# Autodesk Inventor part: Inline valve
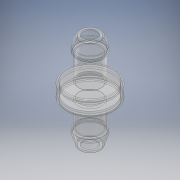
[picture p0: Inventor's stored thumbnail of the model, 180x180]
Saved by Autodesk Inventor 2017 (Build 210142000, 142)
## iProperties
Created: 2020-03
Part Number: Inline valve
Material: Polycarbonate, Clear
Document SubType Name: Modeling
Designer: user
Density: 1.2 g/cm^3
Appearance: Polycarbonate - Clear
Author: user
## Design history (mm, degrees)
sketch "Sketch1"
  geometry: L1 (6.465, 0)-(8.681, 0); L2 (11.059, -37.6)-(20.7, -37.6); L3 (22.7, -39.6)-(22.7, -50.6); L4 (20.7, -52.6)-(11.059, -52.6); L5 (8.681, -90.177)-(6.465, -90.177); L6 (9.636, -0.704)-(12.251, -9.128); L7 (12.7, -13.598)-(12.059, -13.598); L8 (11.059, -14.598)-(11.059, -37.6); L9 (9.636, -89.473)-(12.7, -79.601); L10 (12.7, -76.579)-(12.059, -76.579); L11 (11.059, -75.579)-(11.059, -52.6); L12 (12.7, -12.092)-(12.7, -13.598); L13 (12.7, -76.579)-(12.7, -79.601); L14 (21.5, -50.6)-(21.5, -39.6); L15 (20.7, -38.8)-(9.859, -38.8); L16 (9.859, -38.8)-(9.859, -14.598); L17 (11.5, -12.47)-(11.5, -12.092); L18 (11.105, -9.484)-(8.534, -1.2); L19 (8.534, -1.2)-(6.465, -1.2); L20 (6.465, -88.977)-(8.534, -88.977); L21 (8.534, -88.977)-(11.5, -79.419); L22 (11.5, -79.419)-(11.5, -77.707); L23 (9.859, -75.579)-(9.859, -51.4); L24 (9.859, -51.4)-(20.7, -51.4); L25 (6.465, 0)-(6.465, -1.2); L26 (6.465, -88.977)-(6.465, -90.177); L27 (0, -108.432)-(0, 18.255) reference; A1 r 2 centre (20.7, -39.6) between (22.7, -39.6) and (20.7, -37.6); A2 r 2 centre (20.7, -50.6) between (20.7, -52.6) and (22.7, -50.6); A3 r 10 centre (2.7, -12.092) between (12.7, -12.092) and (12.251, -9.128); A4 r 1 centre (12.059, -14.598) between (12.059, -13.598) and (11.059, -14.598); A5 r 1 centre (12.059, -75.579) between (11.059, -75.579) and (12.059, -76.579); A6 r 1 centre (8.681, -89.177) between (8.681, -90.177) and (9.636, -89.473); A7 r 1 centre (8.681, -1) between (9.636, -0.704) and (8.681, 0); A8 r 0.8 centre (20.7, -39.6) between (21.5, -39.6) and (20.7, -38.8); A9 r 2.2 centre (12.059, -14.598) between (11.5, -12.47) and (9.859, -14.598); A10 r 8.8 centre (2.7, -12.092) between (11.5, -12.092) and (11.105, -9.484); A11 r 2.2 centre (12.059, -75.579) between (9.859, -75.579) and (11.5, -77.707); A12 r 0.8 centre (20.7, -50.6) between (20.7, -51.4) and (21.5, -50.6); 1 further point
  constraints: 52 end point, 24 point on circle, 13 tangent, 12 centre point, 6 perpendicular, 4 equal radius, 2 vertical, 1 horizontal, 8 other
  dimensions: "d5" = 2 radius of A1 (derived); "d6" = 10 radius of A3 (derived); "d7" = 1 radius of A4; "d8" = 1.2 distance between parallel lines of L3 L14
revolve "Revolution2" sketch "Sketch1" stored, may be unused: angle "d11" = 90 deg
sketch "Sketch2"
  geometry: L1 (0, -40.574)-(20.612, -40.574); L2 (20.612, -40.574)-(20.612, -42.338); L3 (20.612, -42.338)-(0, -42.338); L4 (0, -42.338)-(0, -40.574); L5 (0, -49.626)-(20.612, -49.626); L6 (20.612, -49.626)-(20.612, -47.862); L7 (20.612, -47.862)-(0, -47.862); L8 (0, -47.862)-(0, -49.626); 1 further point
  constraints: 16 end point, 3 perpendicular, 1 horizontal
revolve "Revolution3" sketch "Sketch2" stored, may be unused: angle "d12" = 90 deg
body "Solid2"
